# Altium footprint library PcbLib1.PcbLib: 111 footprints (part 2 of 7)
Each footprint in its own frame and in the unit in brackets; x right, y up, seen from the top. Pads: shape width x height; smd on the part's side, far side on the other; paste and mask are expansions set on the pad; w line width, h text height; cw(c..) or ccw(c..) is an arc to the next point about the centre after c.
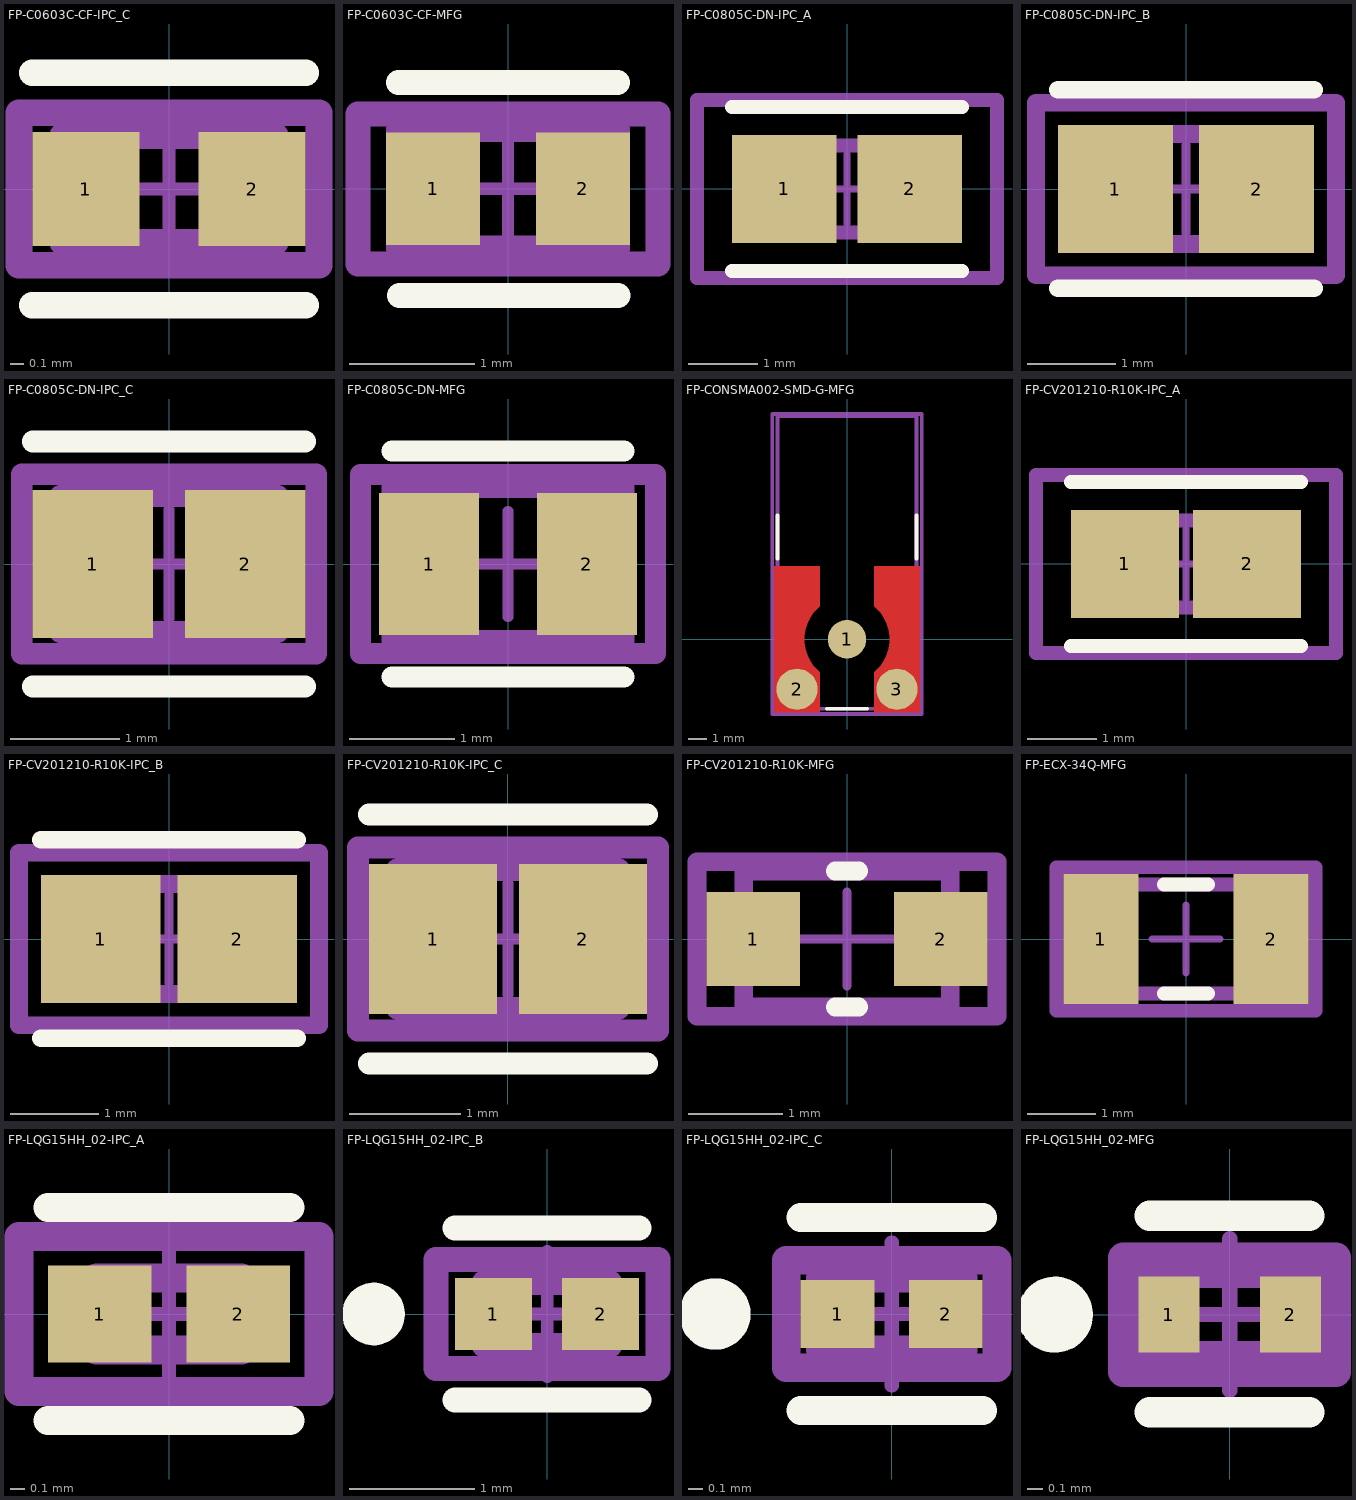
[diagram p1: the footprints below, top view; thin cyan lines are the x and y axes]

## FP-C0603C-CF-IPC_C [mm]
pads (2):
  rect 0.807x0.858 smd paste+0 mask+0: 1(-0.626,0) 2(0.626,0)
Top Overlay:
  lines w0.2: -1.029,-0.875 1.029,-0.875 ; -1.029,0.875 1.029,0.875
Mechanical 5:
  lines w0.2: -1.129,-0.575 -1.129,0.575 1.129,0.575 1.129,-0.575 -1.129,-0.575
  text ".Designator" at 0,0.188 h1
Mechanical 13:
  lines w0.2: -0.8,-0.4 -0.8,0.4 0.8,0.4 0.8,-0.4 -0.8,-0.4
Mechanical 15:
  lines w0.2: -1.129,-0.575 -1.129,0.575 1.129,0.575 1.129,-0.575 -1.129,-0.575
Mechanical 16:
  lines w0.1: -0.5,0 0.5,0 ; 0,-0.5 0,0.5
3D body "Cap_KEMET_C0603C272M5JACTU_eec.STEP": height 0.25, standoff 0, extent -1.129,-0.575 1.129,0.575

## FP-C0603C-CF-MFG [mm]
pads (2):
  rect 0.75x0.9 smd paste+0 mask+0: 1(-0.6,0) 2(0.6,0)
Top Overlay:
  lines w0.2: -0.875,0.85 0.875,0.85 ; -0.87,-0.853 0.88,-0.853
Mechanical 5:
  lines w0.2: -1.2,-0.6 1.2,-0.6 1.2,0.6 -1.2,0.6 -1.2,-0.6
  text ".Designator" at 0,0.188 h1
Mechanical 13:
  lines w0.2: -0.875,-0.475 0.875,-0.475 0.875,0.475 -0.875,0.475 -0.875,-0.475
Mechanical 15:
  lines w0.2: -1.2,-0.6 1.2,-0.6 1.2,0.6 -1.2,0.6 -1.2,-0.6
Mechanical 16:
  lines w0.1: -0.5,0 0.5,0 ; 0,-0.5 0,0.5
3D body "Cap_KEMET_C0603C272M5JACTU_eec.STEP": height 0.25, standoff 0, extent -1.2,-0.6 1.2,0.6

## FP-C0805C-DN-IPC_A [mm]
pads (2):
  rect 1.505x1.556 smd paste+0 mask+0: 1(-0.901,0) 2(0.901,0)
Top Overlay:
  lines w0.2: -1.653,-1.178 1.653,-1.178 ; -1.653,1.178 1.653,1.178
Mechanical 5:
  lines w0.2: -2.153,-1.278 2.153,-1.278 2.153,1.278 -2.153,1.278 -2.153,-1.278
  text ".Designator" at 0,0.188 h1
Mechanical 13:
  lines w0.2: -1,-0.625 1,-0.625 1,0.625 -1,0.625 -1,-0.625
Mechanical 15:
  lines w0.2: -2.153,-1.278 2.153,-1.278 2.153,1.278 -2.153,1.278 -2.153,-1.278
Mechanical 16:
  lines w0.1: -0.5,0 0.5,0 ; 0,-0.5 0,0.5
3D body "Cap_KEMET_C0805C472J3HAC_eec.STEP": height 0.25, standoff 0, extent -2.153,-1.278 2.153,1.278

## FP-C0805C-DN-IPC_B [mm]
pads (2):
  rect 1.305x1.456 smd paste+0 mask+0: 1(-0.801,0) 2(0.801,0)
Top Overlay:
  lines w0.2: -1.453,-1.128 1.453,-1.128 ; -1.453,1.128 1.453,1.128
Mechanical 5:
  lines w0.2: -1.703,-0.978 1.703,-0.978 1.703,0.978 -1.703,0.978 -1.703,-0.978
  text ".Designator" at 0,0.188 h1
Mechanical 13:
  lines w0.2: -1,-0.625 1,-0.625 1,0.625 -1,0.625 -1,-0.625
Mechanical 15:
  lines w0.2: -1.703,-0.978 1.703,-0.978 1.703,0.978 -1.703,0.978 -1.703,-0.978
Mechanical 16:
  lines w0.1: -0.5,0 0.5,0 ; 0,-0.5 0,0.5
3D body "Cap_KEMET_C0805C472J3HAC_eec.STEP": height 0.25, standoff 0, extent -1.703,-0.978 1.703,0.978

## FP-C0805C-DN-IPC_C [mm]
pads (2):
  rect 1.105x1.356 smd paste+0 mask+0: 1(-0.701,0) 2(0.701,0)
Top Overlay:
  lines w0.2: -1.253,-1.125 1.253,-1.125 ; -1.253,1.125 1.253,1.125
Mechanical 5:
  lines w0.2: -1.353,-0.825 -1.353,0.825 1.353,0.825 1.353,-0.825 -1.353,-0.825
  text ".Designator" at 0,0.188 h1
Mechanical 13:
  lines w0.2: -1,-0.625 -1,0.625 1,0.625 1,-0.625 -1,-0.625
Mechanical 15:
  lines w0.2: -1.353,-0.825 -1.353,0.825 1.353,0.825 1.353,-0.825 -1.353,-0.825
Mechanical 16:
  lines w0.1: -0.5,0 0.5,0 ; 0,-0.5 0,0.5
3D body "Cap_KEMET_C0805C472J3HAC_eec.STEP": height 0.25, standoff 0, extent -1.353,-0.825 1.353,0.825

## FP-C0805C-DN-MFG [mm]
pads (2):
  rect 0.95x1.35 smd paste+0 mask+0: 1(-0.75,0) 2(0.75,0)
Top Overlay:
  lines w0.2: -1.1,-1.075 1.1,-1.075 ; -1.1,1.075 1.1,1.075
Mechanical 5:
  lines w0.2: -1.4,-0.85 1.4,-0.85 1.4,0.85 -1.4,0.85 -1.4,-0.85
  text ".Designator" at 0,0.188 h1
Mechanical 13:
  lines w0.2: -1.1,-0.725 1.1,-0.725 1.1,0.725 -1.1,0.725 -1.1,-0.725
Mechanical 15:
  lines w0.2: -1.4,-0.85 1.4,-0.85 1.4,0.85 -1.4,0.85 -1.4,-0.85
Mechanical 16:
  lines w0.1: -0.5,0 0.5,0 ; 0,-0.5 0,0.5
3D body "Cap_KEMET_C0805C472J3HAC_eec.STEP": height 0.25, standoff 0, extent -1.4,-0.85 1.4,0.85

## FP-CONSMA002-SMD-G-MFG [mm]
pads (3):
  round 2.05 smd paste+0 mask+0: 1(0,0)
  round 2.196 smd paste+0 mask+0: 2(-2.66,-2.66) 3(2.66,-2.66)
Top Layer:
  region: -3.88,3.88 -3.88,-3.88 -1.44,-3.88 -1.44,-1.768 -1.567,-1.657 -1.794,-1.408 -1.981,-1.128 -2.126,-0.824 -2.224,-0.502 -2.274,-0.168 -2.274,0.168 -2.224,0.502 -2.126,0.824 -1.981,1.128 -1.794,1.408 -1.567,1.657 -1.44,1.768 -1.44,3.88
  region: 3.88,3.88 3.88,-3.88 1.44,-3.88 1.44,-1.768 1.567,-1.657 1.794,-1.408 1.981,-1.128 2.126,-0.824 2.224,-0.502 2.274,-0.168 2.274,0.168 2.224,0.502 2.126,0.824 1.981,1.128 1.794,1.408 1.567,1.657 1.44,1.768 1.44,3.88
Top Overlay:
  lines w0.2: -3.7,4.3 -3.7,6.6 ; -1.065,-3.7 1.065,-3.7 ; 3.7,4.3 3.7,6.6
Mechanical 5:
  lines w0.2: -3.98,-3.98 3.98,-3.98 3.98,12 -3.98,12 -3.98,-3.98
  text ".Designator" at 0,4.009 h1
Mechanical 13:
  lines w0.2: -3.7,-3.7 3.7,-3.7 3.7,11.9 -3.7,11.9 -3.7,-3.7
Mechanical 15:
  lines w0.2: -3.98,-3.98 3.98,-3.98 3.98,12 -3.98,12 -3.98,-3.98
Mechanical 16:
  lines w0.1: -0.5,0 0.5,0 ; 0,-0.5 0,0.5
3D body "Conn_Linx_Technologies_CONSMA002-SMD-G_eec.STEP": height 0.25, standoff 0, extent -3.98,-3.98 3.98,12

## FP-CV201210-R10K-IPC_A [mm]
pads (2):
  rect 1.554x1.556 smd paste+0 mask+0: 1(-0.876,0) 2(0.876,0)
Top Overlay:
  lines w0.2: -1.653,-1.178 1.653,-1.178 ; -1.653,1.178 1.653,1.178
Mechanical 5:
  lines w0.2: -2.153,-1.278 2.153,-1.278 2.153,1.278 -2.153,1.278 -2.153,-1.278
  text ".Designator" at 0,0.188 h1
Mechanical 13:
  lines w0.2: -1,-0.625 1,-0.625 1,0.625 -1,0.625 -1,-0.625
Mechanical 15:
  lines w0.2: -2.153,-1.278 2.153,-1.278 2.153,1.278 -2.153,1.278 -2.153,-1.278
Mechanical 16:
  lines w0.1: -0.5,0 0.5,0 ; 0,-0.5 0,0.5
3D body "Ind_Bourns_CV201210-R10K_eec.STEP": height 0.25, standoff 0, extent -2.153,-1.278 2.153,1.278

## FP-CV201210-R10K-IPC_B [mm]
pads (2):
  rect 1.354x1.456 smd paste+0 mask+0: 1(-0.776,0) 2(0.776,0)
Top Overlay:
  lines w0.2: -1.453,-1.128 1.453,-1.128 ; -1.453,1.128 1.453,1.128
Mechanical 5:
  lines w0.2: -1.703,-0.978 -1.703,0.978 1.703,0.978 1.703,-0.978 -1.703,-0.978
  text ".Designator" at 0,0.188 h1
Mechanical 13:
  lines w0.2: -1,-0.625 -1,0.625 1,0.625 1,-0.625 -1,-0.625
Mechanical 15:
  lines w0.2: -1.703,-0.978 -1.703,0.978 1.703,0.978 1.703,-0.978 -1.703,-0.978
Mechanical 16:
  lines w0.1: -0.5,0 0.5,0 ; 0,-0.5 0,0.5
3D body "Ind_Bourns_CV201210-R10K_eec.STEP": height 0.25, standoff 0, extent -1.703,-0.978 1.703,0.978

## FP-CV201210-R10K-IPC_C [mm]
pads (2):
  rect 1.154x1.356 smd paste+0 mask+0: 1(-0.676,0) 2(0.676,0)
Top Overlay:
  lines w0.2: -1.253,-1.125 1.253,-1.125 ; -1.253,1.125 1.253,1.125
Mechanical 5:
  lines w0.2: -1.353,-0.825 -1.353,0.825 1.353,0.825 1.353,-0.825 -1.353,-0.825
  text ".Designator" at 0,0.188 h1
Mechanical 13:
  lines w0.2: -1,-0.625 -1,0.625 1,0.625 1,-0.625 -1,-0.625
Mechanical 15:
  lines w0.2: -1.353,-0.825 -1.353,0.825 1.353,0.825 1.353,-0.825 -1.353,-0.825
Mechanical 16:
  lines w0.1: -0.5,0 0.5,0 ; 0,-0.5 0,0.5
3D body "Ind_Bourns_CV201210-R10K_eec.STEP": height 0.25, standoff 0, extent -1.353,-0.825 1.353,0.825

## FP-CV201210-R10K-MFG [mm]
pads (2):
  rect 1x1 smd paste+0 mask+0: 1(-1,0) 2(1,0)
Top Overlay:
  lines w0.2: -0.125,-0.725 0.125,-0.725 ; -0.125,0.725 0.125,0.725
Mechanical 5:
  lines w0.2: -1.6,-0.825 1.6,-0.825 1.6,0.825 -1.6,0.825 -1.6,-0.825
  text ".Designator" at 0,0.188 h1
Mechanical 13:
  lines w0.2: -1.1,-0.725 1.1,-0.725 1.1,0.725 -1.1,0.725 -1.1,-0.725
Mechanical 15:
  lines w0.2: -1.6,-0.825 1.6,-0.825 1.6,0.825 -1.6,0.825 -1.6,-0.825
Mechanical 16:
  lines w0.1: -0.5,0 0.5,0 ; 0,-0.5 0,0.5
3D body "Ind_Bourns_CV201210-R10K_eec.STEP": height 0.25, standoff 0, extent -1.6,-0.825 1.6,0.825

## FP-ECX-34Q-MFG [mm]
pads (2):
  rect 1.1x1.9 smd paste+0 mask+0: 1(-1.25,0) 2(1.25,0)
Top Overlay:
  lines w0.2: -0.325,-0.8 0.325,-0.8 ; -0.325,0.8 0.325,0.8
Mechanical 5:
  lines w0.2: -1.9,-1.05 -1.9,1.05 1.9,1.05 1.9,-1.05 -1.9,-1.05
  text ".Designator" at 0,0.188 h1
Mechanical 13:
  lines w0.2: -1.65,-0.8 -1.65,0.8 1.65,0.8 1.65,-0.8 -1.65,-0.8
Mechanical 15:
  lines w0.2: -1.9,-1.05 -1.9,1.05 1.9,1.05 1.9,-1.05 -1.9,-1.05
Mechanical 16:
  lines w0.1: -0.5,0 0.5,0 ; 0,-0.5 0,0.5
3D body "Crys_ECS_International_ECS-_327-12_5-34QCS-TR_eec.STEP": height 0.25, standoff 0, extent -1.9,-1.05 1.9,1.05

## FP-LQG15HH_02-IPC_A [mm]
pads (2):
  rect 0.715x0.672 smd paste+0 mask+0: 1(-0.479,0) 2(0.479,0)
Top Overlay:
  lines w0.2: -0.836,-0.736 0.836,-0.736 ; -0.836,0.736 0.836,0.736
Mechanical 5:
  lines w0.2: -1.036,-0.536 -1.036,0.536 1.036,0.536 1.036,-0.536 -1.036,-0.536
  text ".Designator" at 0,-0.001 h1
Mechanical 13:
  lines w0.2: -0.5,-0.25 -0.5,0.25 0.5,0.25 0.5,-0.25 -0.5,-0.25
Mechanical 15:
  lines w0.2: -1.036,-0.536 -1.036,0.536 1.036,0.536 1.036,-0.536 -1.036,-0.536
Mechanical 16:
  lines w0.1: -0.5,0 0.5,0 ; 0,-0.5 0,0.5
3D body "Ind_Murata_LQG15HN39NJ02D_eec.STEP": height 0.25, standoff 0, extent -1.036,-0.536 1.036,0.536

## FP-LQG15HH_02-IPC_B [mm]
pads (2):
  rect 0.615x0.572 smd paste+0 mask+0: 1(-0.429,0) 2(0.429,0)
Top Overlay:
  circle w0.25: c-1.386,0 r0.125
  lines w0.2: -0.736,-0.686 0.736,-0.686 ; -0.736,0.686 0.736,0.686
Mechanical 5:
  lines w0.2: -0.886,-0.436 0.886,-0.436 0.886,0.436 -0.886,0.436 -0.886,-0.436
  text ".Designator" at 0,-0.001 h1
Mechanical 13:
  lines w0.2: -0.5,-0.25 0.5,-0.25 0.5,0.25 -0.5,0.25 -0.5,-0.25
Mechanical 15:
  lines w0.2: -0.886,-0.436 0.886,-0.436 0.886,0.436 -0.886,0.436 -0.886,-0.436
Mechanical 16:
  lines w0.1: -0.5,0 0.5,0 ; 0,-0.5 0,0.5
3D body "Ind_Murata_LQG15HN39NJ02D_eec.STEP": height 0.25, standoff 0, extent -0.886,-0.436 0.886,0.436

## FP-LQG15HH_02-IPC_C [mm]
pads (2):
  rect 0.515x0.472 smd paste+0 mask+0: 1(-0.379,0) 2(0.379,0)
Top Overlay:
  circle w0.25: c-1.236,0 r0.125
  lines w0.2: -0.636,-0.675 0.636,-0.675 ; -0.636,0.675 0.636,0.675
Mechanical 5:
  lines w0.2: -0.736,-0.375 -0.736,0.375 0.736,0.375 0.736,-0.375 -0.736,-0.375
  text ".Designator" at 0,-0.001 h1
Mechanical 13:
  lines w0.2: -0.5,-0.25 -0.5,0.25 0.5,0.25 0.5,-0.25 -0.5,-0.25
Mechanical 15:
  lines w0.2: -0.736,-0.375 -0.736,0.375 0.736,0.375 0.736,-0.375 -0.736,-0.375
Mechanical 16:
  lines w0.1: -0.5,0 0.5,0 ; 0,-0.5 0,0.5
3D body "Ind_Murata_LQG15HN39NJ02D_eec.STEP": height 0.25, standoff 0, extent -0.736,-0.375 0.736,0.375

## FP-LQG15HH_02-MFG [mm]
pads (2):
  rect 0.4x0.5 smd paste+0 mask+0: 1(-0.4,0) 2(0.4,0)
Top Overlay:
  circle w0.25: c-1.15,0 r0.125
  lines w0.2: -0.525,-0.642 0.525,-0.642 ; -0.525,0.65 0.525,0.65
Mechanical 5:
  lines w0.2: -0.7,-0.375 0.7,-0.375 0.7,0.375 -0.7,0.375 -0.7,-0.375
  text ".Designator" at 0,-0.001 h1
Mechanical 13:
  lines w0.2: -0.525,-0.275 0.525,-0.275 0.525,0.275 -0.525,0.275 -0.525,-0.275
Mechanical 15:
  lines w0.2: -0.7,-0.375 0.7,-0.375 0.7,0.375 -0.7,0.375 -0.7,-0.375
Mechanical 16:
  lines w0.1: -0.5,0 0.5,0 ; 0,-0.5 0,0.5
3D body "Ind_Murata_LQG15HN39NJ02D_eec.STEP": height 0.25, standoff 0, extent -0.7,-0.375 0.7,0.375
